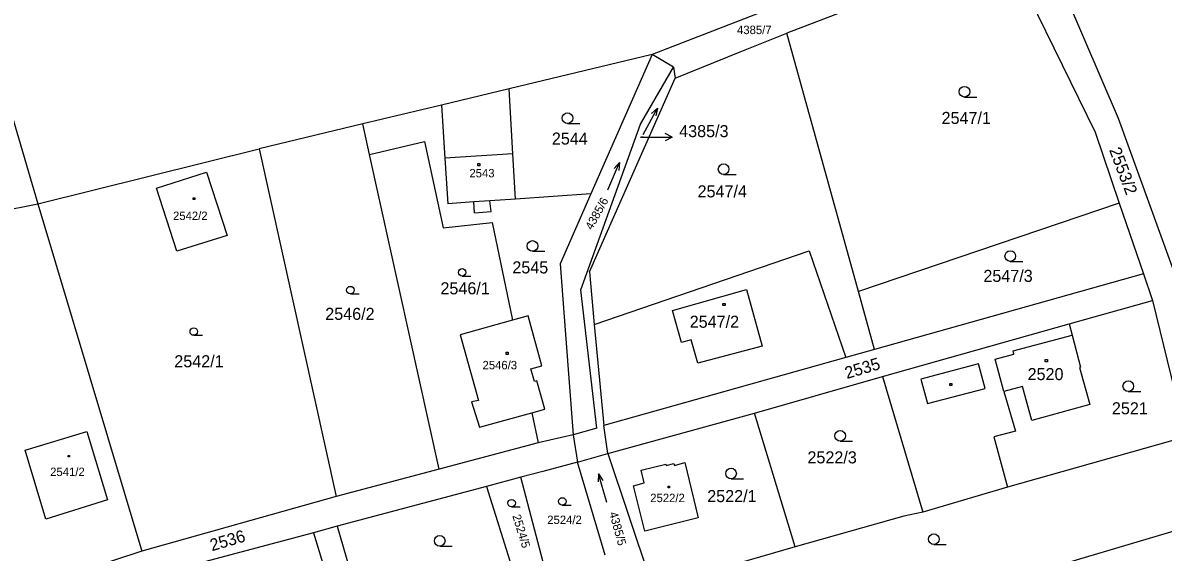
# Model space of a CAD drawing. Extents: x -468021 to -466942, y -1130484 to -1128584.
# Drawn here: x -467879.7 to -467719, y -1129681.1 to -1129606.5 of the extents above; entities that cross this region are included whole.
import ezdxf

# ---------------------------------------------------------------- set-up
doc = ezdxf.new("R2010")
doc.units = 0
doc.layers.add('DKM', color=7, linetype='Continuous')

msp = doc.modelspace()

# ---------------------------------------------------------------- linework, layer by layer
at = {"layer": 'DKM'}
for p, q in [((-467892.26, -1129582.14), (-467877.54, -1129632.02)), ((-467725.28, -1129619.99), (-467736.76, -1129593.28)), ((-467741.1, -1129596.38), (-467728.59, -1129621.95)), ((-467763.37, -1129600.27), (-467790.98, -1129610.98)), ((-467761.68, -1129604.05), (-467772.03, -1129608)), ((-467778.58, -1129610.6), (-467772.03, -1129608)), ((-467761.94, -1129644.37), (-467772.03, -1129608)), ((-467787.78, -1129614.34), (-467778.58, -1129610.6)), ((-467790.98, -1129610.98), (-467811.17, -1129615.83)), ((-467790.98, -1129610.98), (-467799.63, -1129630.65)), ((-467787.97, -1129612.77), (-467790.98, -1129610.98)), ((-467792.64, -1129620.81), (-467787.97, -1129612.77)), ((-467787.97, -1129612.77), (-467787.78, -1129614.34)), ((-467799.85, -1129641.62), (-467787.78, -1129614.34)), ((-467811.17, -1129615.83), (-467820.69, -1129618.12)), ((-467810.62, -1129624.99), (-467811.17, -1129615.83)), ((-467747, -1129616.99), (-467745.25, -1129616.99)), ((-467820.69, -1129618.12), (-467831.77, -1129620.78)), ((-467820.69, -1129618.12), (-467820.2, -1129625.61)), ((-467792.27, -1129622.25), (-467790.27, -1129618.55)), ((-467790.27, -1129618.55), (-467791.08, -1129619.31)), ((-467790.27, -1129618.55), (-467790.46, -1129619.64)), ((-467716.56, -1129644.13), (-467725.28, -1129619.99)), ((-467831.77, -1129620.78), (-467846.36, -1129624.28)), ((-467830.82, -1129625.07), (-467831.77, -1129620.78)), ((-467802.92, -1129620.71), (-467801.17, -1129620.71)), ((-467801.07, -1129644.14), (-467792.64, -1129620.81)), ((-467788.19, -1129622.64), (-467789.19, -1129622.14)), ((-467728.59, -1129621.95), (-467725.18, -1129631.95)), ((-467830.82, -1129625.07), (-467823.09, -1129623.27)), ((-467823.09, -1129623.27), (-467820.44, -1129635.4)), ((-467792.65, -1129622.64), (-467791.19, -1129622.64)), ((-467791.19, -1129622.64), (-467788.19, -1129622.64)), ((-467788.19, -1129622.64), (-467789.19, -1129623.14)), ((-467877.54, -1129632.02), (-467846.36, -1129624.28)), ((-467846.36, -1129624.28), (-467835.51, -1129673.29)), ((-467821.03, -1129669.43), (-467830.82, -1129625.07)), ((-467810.62, -1129624.99), (-467820.2, -1129625.61)), ((-467810.24, -1129631.37), (-467810.62, -1129624.99)), ((-467820.2, -1129625.61), (-467819.78, -1129632.02)), ((-467815.56, -1129626.36), (-467815.26, -1129626.36)), ((-467815.56, -1129626.66), (-467815.56, -1129626.36)), ((-467815.26, -1129626.66), (-467815.56, -1129626.66)), ((-467815.26, -1129626.36), (-467815.26, -1129626.66)), ((-467797.25, -1129630.08), (-467795.61, -1129626.22)), ((-467795.61, -1129626.22), (-467796.34, -1129627.05)), ((-467795.61, -1129626.22), (-467795.7, -1129627.32)), ((-467860.82, -1129629.81), (-467853.79, -1129627.58)), ((-467853.79, -1129627.58), (-467850.88, -1129636.48)), ((-467780.93, -1129627.9), (-467779.18, -1129627.9)), ((-467857.99, -1129638.71), (-467860.82, -1129629.81)), ((-467855.66, -1129631.2), (-467855.45, -1129631.2)), ((-467855.66, -1129631.41), (-467855.66, -1129631.2)), ((-467855.45, -1129631.41), (-467855.66, -1129631.41)), ((-467855.45, -1129631.2), (-467855.45, -1129631.41)), ((-467816.14, -1129631.77), (-467819.78, -1129632.02)), ((-467813.87, -1129631.62), (-467816.14, -1129631.77)), ((-467816.04, -1129633.3), (-467816.14, -1129631.77)), ((-467810.24, -1129631.37), (-467813.87, -1129631.62)), ((-467813.69, -1129633.14), (-467813.87, -1129631.62)), ((-467799.63, -1129630.65), (-467810.24, -1129631.37)), ((-467799.63, -1129630.65), (-467803.97, -1129640.51)), ((-467906.2, -1129637.77), (-467877.54, -1129632.02)), ((-467877.54, -1129632.02), (-467862.9, -1129680.96)), ((-467816.04, -1129633.3), (-467813.69, -1129633.14)), ((-467725.18, -1129631.95), (-467761.94, -1129644.37)), ((-467725.18, -1129631.95), (-467721.78, -1129641.91)), ((-467820.44, -1129635.4), (-467813.52, -1129634.69)), ((-467813.52, -1129634.69), (-467810.66, -1129648.44)), ((-467850.88, -1129636.48), (-467857.99, -1129638.71)), ((-467807.85, -1129638.72), (-467806.1, -1129638.72)), ((-467799.16, -1129649.03), (-467768.9, -1129638.64)), ((-467768.9, -1129638.64), (-467763.7, -1129653.68)), ((-467803.97, -1129640.51), (-467803.22, -1129650.43)), ((-467740.54, -1129640.15), (-467738.79, -1129640.15)), ((-467817.77, -1129642.21), (-467816.54, -1129642.21)), ((-467799.85, -1129641.62), (-467799.16, -1129649.03)), ((-467721.78, -1129641.91), (-467759.67, -1129652.55)), ((-467721.78, -1129641.91), (-467720.49, -1129645.67)), ((-467798.8, -1129663.66), (-467801.07, -1129644.14)), ((-467788.14, -1129647.08), (-467777.73, -1129644.11)), ((-467777.73, -1129644.11), (-467775.5, -1129652.08)), ((-467759.67, -1129652.55), (-467761.94, -1129644.37)), ((-467833.52, -1129644.71), (-467832.29, -1129644.71)), ((-467781.03, -1129646.06), (-467780.73, -1129646.06)), ((-467781.03, -1129646.36), (-467781.03, -1129646.06)), ((-467780.73, -1129646.06), (-467780.73, -1129646.36)), ((-467732.24, -1129648.97), (-467720.49, -1129645.67)), ((-467720.49, -1129645.67), (-467715.79, -1129664.86)), ((-467808.49, -1129647.84), (-467810.66, -1129648.44)), ((-467806.54, -1129654.87), (-467808.49, -1129647.84)), ((-467786.86, -1129651.6), (-467788.14, -1129647.08)), ((-467780.73, -1129646.36), (-467781.03, -1129646.36)), ((-467810.66, -1129648.44), (-467818.04, -1129650.49)), ((-467799.16, -1129649.03), (-467797.83, -1129663.26)), ((-467758.56, -1129656.37), (-467732.24, -1129648.97)), ((-467732.24, -1129648.97), (-467731.84, -1129650.55)), ((-467855.59, -1129650.56), (-467854.36, -1129650.56)), ((-467818.04, -1129650.49), (-467815.49, -1129659.76)), ((-467803.22, -1129650.43), (-467802.15, -1129664.59)), ((-467740.14, -1129652.77), (-467731.84, -1129650.55)), ((-467731.84, -1129650.55), (-467730.65, -1129655.04)), ((-467785.49, -1129651.22), (-467786.86, -1129651.6)), ((-467784.57, -1129654.47), (-467785.49, -1129651.22)), ((-467775.5, -1129652.08), (-467784.57, -1129654.47)), ((-467759.67, -1129652.55), (-467763.7, -1129653.68)), ((-467811.58, -1129652.95), (-467811.28, -1129652.95)), ((-467811.58, -1129653.25), (-467811.58, -1129652.95)), ((-467811.28, -1129653.25), (-467811.58, -1129653.25)), ((-467811.28, -1129652.95), (-467811.28, -1129653.25)), ((-467763.7, -1129653.68), (-467797.83, -1129663.26)), ((-467742.66, -1129653.94), (-467740.06, -1129653.23)), ((-467741.43, -1129658.49), (-467742.66, -1129653.94)), ((-467740.06, -1129653.23), (-467740.14, -1129652.77)), ((-467735.61, -1129653.98), (-467735.31, -1129653.98)), ((-467735.61, -1129654.28), (-467735.61, -1129653.98)), ((-467735.31, -1129654.28), (-467735.61, -1129654.28)), ((-467735.31, -1129653.98), (-467735.31, -1129654.28)), ((-467808.08, -1129655.29), (-467806.54, -1129654.87)), ((-467807.59, -1129657.06), (-467808.08, -1129655.29)), ((-467745, -1129654.6), (-467753.15, -1129656.76)), ((-467744.06, -1129658.08), (-467745, -1129654.6)), ((-467730.65, -1129655.04), (-467730.79, -1129655.08)), ((-467730.79, -1129655.08), (-467729.35, -1129660.33)), ((-467807.24, -1129656.96), (-467807.59, -1129657.06)), ((-467806.12, -1129660.98), (-467807.24, -1129656.96)), ((-467776.58, -1129661.55), (-467758.56, -1129656.37)), ((-467758.56, -1129656.37), (-467752.87, -1129675.47)), ((-467753.15, -1129656.76), (-467752.21, -1129660.19)), ((-467749.08, -1129657.35), (-467748.78, -1129657.35)), ((-467749.08, -1129657.65), (-467749.08, -1129657.35)), ((-467748.78, -1129657.35), (-467748.78, -1129657.65)), ((-467752.21, -1129660.19), (-467744.06, -1129658.08)), ((-467748.78, -1129657.65), (-467749.08, -1129657.65)), ((-467738.8, -1129657.78), (-467741.43, -1129658.49)), ((-467741.43, -1129658.49), (-467739.81, -1129664.07)), ((-467737.51, -1129662.58), (-467738.8, -1129657.78)), ((-467723.91, -1129658.48), (-467722.16, -1129658.48)), ((-467815.49, -1129659.76), (-467816.45, -1129659.93)), ((-467816.45, -1129659.93), (-467815.31, -1129663.53)), ((-467729.35, -1129660.33), (-467737.51, -1129662.58)), ((-467815.31, -1129663.53), (-467807.95, -1129661.49)), ((-467807.95, -1129661.49), (-467806.12, -1129660.98)), ((-467807.95, -1129661.49), (-467807.07, -1129665.7)), ((-467797.25, -1129667.21), (-467776.58, -1129661.55)), ((-467770.83, -1129680.36), (-467776.58, -1129661.55)), ((-467798.8, -1129663.66), (-467802.15, -1129664.59)), ((-467797.25, -1129667.21), (-467797.83, -1129663.26)), ((-467879.32, -1129666.73), (-467870.66, -1129664.11)), ((-467870.66, -1129664.11), (-467867.74, -1129673.77)), ((-467802.15, -1129664.59), (-467807.07, -1129665.7)), ((-467802.15, -1129664.59), (-467801.54, -1129668.44)), ((-467764.51, -1129665.47), (-467762.76, -1129665.47)), ((-467739.81, -1129664.07), (-467742.86, -1129664.87)), ((-467742.86, -1129664.87), (-467740.93, -1129671.98)), ((-467715.79, -1129664.86), (-467740.93, -1129671.98)), ((-467876.42, -1129676.45), (-467879.32, -1129666.73)), ((-467807.07, -1129665.7), (-467821.03, -1129669.43)), ((-467873.3, -1129667.48), (-467873.09, -1129667.48)), ((-467873.3, -1129667.69), (-467873.3, -1129667.48)), ((-467873.09, -1129667.69), (-467873.3, -1129667.69)), ((-467873.09, -1129667.48), (-467873.09, -1129667.69)), ((-467801.54, -1129668.44), (-467806.42, -1129669.75)), ((-467801.54, -1129668.44), (-467797.25, -1129667.21)), ((-467797.6, -1129681.56), (-467801.54, -1129668.44)), ((-467797.25, -1129667.21), (-467790.91, -1129686.15)), ((-467792.55, -1129669.57), (-467789.07, -1129668.71)), ((-467789.07, -1129668.71), (-467789.03, -1129668.92)), ((-467789.03, -1129668.92), (-467787.94, -1129668.64)), ((-467787.94, -1129668.64), (-467787.87, -1129668.93)), ((-467787.87, -1129668.93), (-467786.41, -1129668.5)), ((-467786.41, -1129668.5), (-467784.52, -1129676.29)), ((-467821.03, -1129669.43), (-467835.51, -1129673.29)), ((-467806.42, -1129669.75), (-467809.48, -1129670.56)), ((-467798.57, -1129670.1), (-467798.6, -1129671.2)), ((-467797.37, -1129674.12), (-467798.57, -1129670.1)), ((-467798.57, -1129670.1), (-467797.93, -1129671)), ((-467792.12, -1129671.33), (-467792.55, -1129669.57)), ((-467814.36, -1129671.87), (-467835.37, -1129677.48)), ((-467809.48, -1129670.56), (-467814.36, -1129671.87)), ((-467814.36, -1129671.87), (-467810.02, -1129685.66)), ((-467805.91, -1129684.3), (-467809.48, -1129670.56)), ((-467793.64, -1129671.77), (-467792.12, -1129671.33)), ((-467792.05, -1129678.16), (-467793.64, -1129671.77)), ((-467788.76, -1129671.83), (-467788.55, -1129671.83)), ((-467788.76, -1129672.04), (-467788.76, -1129671.83)), ((-467788.55, -1129671.83), (-467788.55, -1129672.04)), ((-467779.88, -1129670.78), (-467778.13, -1129670.78)), ((-467740.93, -1129671.98), (-467752.87, -1129675.47)), ((-467835.51, -1129673.29), (-467862.9, -1129680.96)), ((-467788.55, -1129672.04), (-467788.76, -1129672.04)), ((-467867.74, -1129673.77), (-467876.42, -1129676.45)), ((-467810.8, -1129674.73), (-467809.58, -1129674.73)), ((-467803.66, -1129674.49), (-467802.43, -1129674.49)), ((-467784.52, -1129676.29), (-467792.05, -1129678.16)), ((-467755.53, -1129676.05), (-467770.83, -1129680.36)), ((-467752.87, -1129675.47), (-467755.53, -1129676.05)), ((-467838.73, -1129678.38), (-467859.18, -1129683.85)), ((-467835.37, -1129677.48), (-467838.73, -1129678.38)), ((-467838.73, -1129678.38), (-467824.94, -1129723.51)), ((-467835.37, -1129677.48), (-467830.6, -1129694.02)), ((-467743.82, -1129685.91), (-467713.27, -1129676.88)), ((-467862.9, -1129680.96), (-467888.61, -1129689.4)), ((-467820.93, -1129680.28), (-467819.18, -1129680.28)), ((-467770.83, -1129680.36), (-467790.91, -1129686.15)), ((-467751.32, -1129680.04), (-467749.57, -1129680.04))]:
    msp.add_line(p, q, dxfattribs=at)
for centre, radius in [((-467747, -1129616.24), 0.75), ((-467802.92, -1129619.96), 0.75), ((-467780.93, -1129627.15), 0.75), ((-467807.85, -1129637.97), 0.75), ((-467740.54, -1129639.4), 0.75), ((-467817.77, -1129641.69), 0.525), ((-467833.52, -1129644.19), 0.525), ((-467855.59, -1129650.04), 0.525), ((-467723.91, -1129657.73), 0.75), ((-467764.51, -1129664.72), 0.75), ((-467779.88, -1129670.03), 0.75), ((-467803.66, -1129673.97), 0.525), ((-467810.8, -1129674.21), 0.525), ((-467820.93, -1129679.53), 0.75), ((-467751.32, -1129679.29), 0.75)]:
    msp.add_circle(centre, radius, dxfattribs=at)

# ---------------------------------------------------------------- texts
for s, height, p in [('4385/7', 1.19, (-467779.04, -1129608.12)), ('2547/1', 1.7, (-467750.22, -1129620.78)), ('2544', 1.7, (-467805.13, -1129623.69)), ('4385/3', 1.7, (-467787.19, -1129622.64)), ('4385/3', 0.1, (-467792.65, -1129622.64)), ('2543', 1.19, (-467816.75, -1129628.31)), ('2547/4', 1.7, (-467784.6, -1129631.13)), ('2542/2', 1.19, (-467858.51, -1129634.32)), ('2545', 1.7, (-467810.7, -1129641.84)), ('2547/3', 1.7, (-467744.33, -1129643.04)), ('2546/1', 1.7, (-467820.83, -1129644.79)), ('2546/2', 1.7, (-467837.06, -1129648.39)), ('2547/2', 1.7, (-467785.71, -1129649.5)), ('2542/1', 1.7, (-467858.33, -1129655.07)), ('2546/3', 1.19, (-467814.9, -1129655.36)), ('2520', 1.7, (-467738.1, -1129656.88)), ('2521', 1.7, (-467726.22, -1129661.7)), ('2522/3', 1.7, (-467769.12, -1129668.61)), ('2541/2', 1.19, (-467875.82, -1129670.4)), ('2522/2', 1.19, (-467791.27, -1129674.07)), ('2522/1', 1.7, (-467783.24, -1129674.07)), ('2524/2', 1.19, (-467805.78, -1129677.16))]:
    msp.add_text(s, height=height, dxfattribs=at).set_placement(p)
for s, height, rotation, p in [('2553/2', 1.7, 290.7941, (-467726.64, -1129624.44)), ('4385/6', 1.19, 60.9454, (-467799.47, -1129635.81)), ('2535', 1.7, 16.6088, (-467763.57, -1129656.73)), ('2524/5', 1.19, 287.0582, (-467810.71, -1129676)), ('4385/5', 1.19, 285.4516, (-467797.06, -1129675.61)), ('2536', 1.7, 16.5328, (-467853.02, -1129681))]:
    msp.add_text(s, height=height, rotation=rotation, dxfattribs=at).set_placement(p)

doc.saveas('drawing.dxf')
